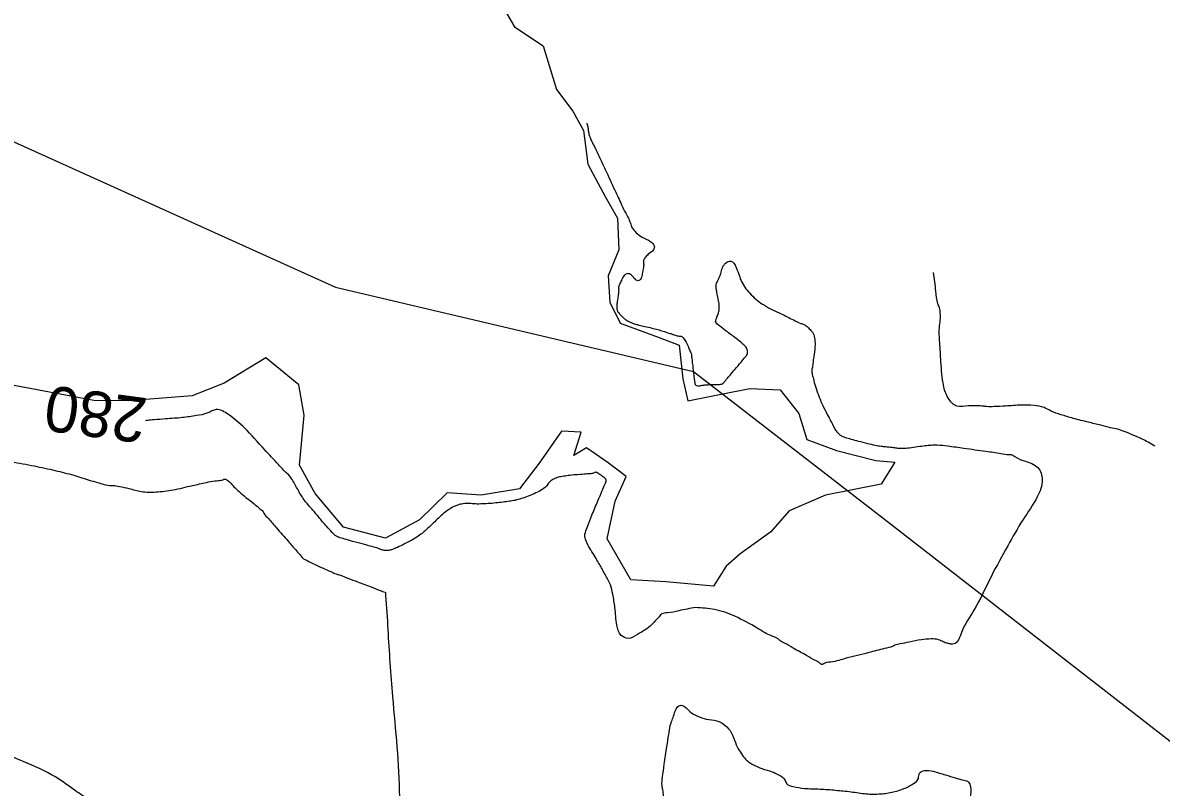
# Model space of a CAD drawing. Extents: x -478464 to -472469, y -1118040 to -1113785.
# Drawn here: x -474559.7 to -474459.6, y -1114309.4 to -1114242.1 of the extents above; entities that cross this region are included whole.
import ezdxf

# ---------------------------------------------------------------- set-up
doc = ezdxf.new("R2010")
doc.units = 0
for name, color, linetype in [('ObPÚ', 7, 'Continuous'), ('vodní plochy', 7, 'Continuous'), ('Vrstevnice_hlavni', 7, 'Continuous'), ('Vrstevnice_popis', 7, 'Continuous'), ('Vrstevnice_vedlejsi', 7, 'Continuous')]:
    doc.layers.add(name, color=color, linetype=linetype)

msp = doc.modelspace()

# ---------------------------------------------------------------- linework, layer by layer
at = {"layer": 'ObPÚ'}
msp.add_lwpolyline([(-474772.3, -1114123.51), (-474725.78, -1114135.53), (-474718.42, -1114145.53), (-474708.56, -1114152.16), (-474646.94, -1114193.59), (-474635.75, -1114203.01), (-474630.46, -1114207.45), (-474607.9, -1114226.4), (-474597.8, -1114234.88), (-474595.52, -1114236.79), (-474532.21, -1114265.39), (-474500.72, -1114272.81), (-474483.66, -1114286.03), (-474436.41, -1114322.73), (-474392.24, -1114354.32), (-474385.18, -1114363.49), (-474350.25, -1114409.55), (-474320.41, -1114444.98)], dxfattribs=at)
at = {"layer": 'vodní plochy'}
msp.add_lwpolyline([(-474517.381, -1114240.932), (-474516.46, -1114242.506), (-474513.936, -1114244.175), (-474512.76, -1114248.017), (-474511.348, -1114249.928), (-474510.41, -1114251.628), (-474510.002, -1114254.59), (-474508.503, -1114257.433), (-474507.396, -1114259.344), (-474507.298, -1114262.119), (-474508.215, -1114264.407), (-474508.087, -1114266.73), (-474507.171, -1114268.554), (-474503.731, -1114269.839), (-474501.992, -1114270.502), (-474501.655, -1114273.476), (-474501.211, -1114275.393), (-474498.281, -1114274.828), (-474495.76, -1114274.328), (-474493.088, -1114274.428), (-474491.467, -1114276.513), (-474490.761, -1114278.81), (-474488.132, -1114279.767), (-474484.696, -1114280.654), (-474483.01, -1114280.807), (-474484.205, -1114282.722), (-474489.099, -1114283.714), (-474492.302, -1114285.085), (-474493.914, -1114286.918), (-474496.657, -1114288.905), (-474497.848, -1114289.962), (-474498.971, -1114291.693), (-474503.166, -1114291.33), (-474506.247, -1114291.163), (-474508.316, -1114287.543), (-474507.623, -1114284.23), (-474506.65, -1114282.069), (-474508.229, -1114280.86), (-474510.129, -1114279.526), (-474511.24, -1114280.205), (-474510.616, -1114278.16), (-474512.335, -1114278.06), (-474514.308, -1114280.889), (-474516.042, -1114283.136), (-474519.386, -1114283.713), (-474522.388, -1114283.51), (-474524.836, -1114285.863), (-474527.818, -1114287.479), (-474531.516, -1114286.517), (-474534.015, -1114283.562), (-474535.382, -1114281.06), (-474534.978, -1114276.657), (-474535.44, -1114274.005), (-474538.342, -1114271.607), (-474542.018, -1114273.852), (-474544.819, -1114274.97), (-474550.403, -1114275.39), (-474553.469, -1114275.387), (-474569.725, -1114272.316)], dxfattribs=at)
at = {"layer": 'Vrstevnice_hlavni'}
for points in [[(-474510.104, -1114250.97), (-474510.091, -1114251.018), (-474510.014, -1114251.351), (-474509.96, -1114251.74), (-474509.859, -1114252.123), (-474509.71, -1114252.502), (-474509.513, -1114252.875), (-474509.103, -1114253.728), (-474508.479, -1114255.061), (-474507.64, -1114256.874), (-474507.041, -1114258.153), (-474506.68, -1114258.898), (-474506.557, -1114259.11), (-474506.422, -1114259.396), (-474506.273, -1114259.758)], [(-474506.273, -1114259.758), (-474506.111, -1114260.194), (-474505.763, -1114260.61), (-474505.229, -1114261.006), (-474504.508, -1114261.383), (-474504.179, -1114261.757), (-474504.243, -1114262.13), (-474504.7, -1114262.502), (-474504.996, -1114262.829), (-474505.131, -1114263.113), (-474505.106, -1114263.352), (-474505.131, -1114263.683), (-474505.208, -1114264.104), (-474505.337, -1114264.617), (-474505.543, -1114264.826), (-474505.826, -1114264.731), (-474506.188, -1114264.332), (-474506.515, -1114264.212), (-474506.807, -1114264.37), (-474507.065, -1114264.806), (-474507.234, -1114265.156), (-474507.313, -1114265.419), (-474507.303, -1114265.596), (-474507.322, -1114265.879), (-474507.37, -1114266.27), (-474507.447, -1114266.768), (-474507.472, -1114267.153), (-474507.445, -1114267.423), (-474507.367, -1114267.579), (-474507.232, -1114267.756), (-474507.04, -1114267.954), (-474506.791, -1114268.173), (-474506.538, -1114268.351), (-474506.281, -1114268.489), (-474506.019, -1114268.587), (-474505.642, -1114268.698), (-474505.148, -1114268.823), (-474504.538, -1114268.961), (-474503.987, -1114269.1), (-474503.496, -1114269.24), (-474503.063, -1114269.38), (-474502.726, -1114269.492), (-474502.482, -1114269.576), (-474502.333, -1114269.633), (-474502.17, -1114269.676), (-474501.991, -1114269.705), (-474501.797, -1114269.721), (-474501.592, -1114269.896), (-474501.375, -1114270.23), (-474501.147, -1114270.724), (-474500.992, -1114271.081), (-474500.91, -1114271.302), (-474500.9, -1114271.385), (-474500.867, -1114271.678), (-474500.811, -1114272.179), (-474500.732, -1114272.888), (-474500.665, -1114273.421), (-474500.611, -1114273.778), (-474500.569, -1114273.96), (-474500.449, -1114274.063), (-474500.25, -1114274.087), (-474499.973, -1114274.034), (-474499.649, -1114273.997), (-474499.277, -1114273.975), (-474498.859, -1114273.97), (-474498.548, -1114273.961), (-474498.344, -1114273.946), (-474498.248, -1114273.927), (-474498.127, -1114273.846), (-474497.98, -1114273.702), (-474497.808, -1114273.495), (-474497.51, -1114273.141), (-474497.084, -1114272.641), (-474496.532, -1114271.992), (-474496.161, -1114271.531), (-474495.97, -1114271.258), (-474495.959, -1114271.171), (-474495.97, -1114271.056), (-474496.002, -1114270.912), (-474496.054, -1114270.74), (-474496.379, -1114270.407), (-474496.976, -1114269.914), (-474497.844, -1114269.26), (-474498.433, -1114268.799), (-474498.743, -1114268.53), (-474498.773, -1114268.455), (-474498.745, -1114268.284), (-474498.658, -1114268.017), (-474498.512, -1114267.656), (-474498.456, -1114267.219), (-474498.49, -1114266.708), (-474498.615, -1114266.122), (-474498.698, -1114265.686), (-474498.74, -1114265.399), (-474498.741, -1114265.263), (-474498.601, -1114264.866), (-474498.32, -1114264.208)], [(-474498.32, -1114264.208), (-474497.898, -1114263.29), (-474497.45, -1114263.108), (-474496.974, -1114263.664), (-474496.471, -1114264.956), (-474495.643, -1114266.068), (-474494.49, -1114266.999), (-474493.012, -1114267.75), (-474491.938, -1114268.282), (-474491.268, -1114268.595), (-474491.003, -1114268.69), (-474490.736, -1114268.866), (-474490.468, -1114269.125), (-474490.199, -1114269.466), (-474490.054, -1114269.978), (-474490.035, -1114270.659), (-474490.141, -1114271.511), (-474490.224, -1114272.138), (-474490.283, -1114272.54), (-474490.318, -1114272.716), (-474490.272, -1114273.074), (-474490.145, -1114273.612), (-474489.937, -1114274.33), (-474489.669, -1114275.067), (-474489.341, -1114275.822), (-474488.953, -1114276.596), (-474488.629, -1114277.225), (-474488.369, -1114277.71), (-474488.171, -1114278.051), (-474487.936, -1114278.316), (-474487.664, -1114278.505), (-474487.355, -1114278.617), (-474486.879, -1114278.762), (-474486.236, -1114278.939), (-474485.427, -1114279.148), (-474484.756, -1114279.299), (-474484.222, -1114279.393), (-474483.825, -1114279.429), (-474483.433, -1114279.47), (-474483.048, -1114279.515), (-474482.668, -1114279.566), (-474482.171, -1114279.564), (-474481.556, -1114279.509), (-474480.824, -1114279.402), (-474480.202, -1114279.327), (-474479.69, -1114279.286), (-474479.289, -1114279.279), (-474478.373, -1114279.368), (-474476.943, -1114279.555), (-474474.999, -1114279.839), (-474473.676, -1114280.026), (-474472.974, -1114280.117), (-474472.894, -1114280.112), (-474472.442, -1114280.304), (-474471.618, -1114280.694), (-474470.422, -1114281.281), (-474470.043, -1114282.336), (-474470.481, -1114283.859), (-474471.737, -1114285.851), (-474473.084, -1114288.173), (-474474.521, -1114290.825), (-474476.049, -1114293.806), (-474477.152, -1114295.796), (-474477.829, -1114296.793), (-474478.08, -1114296.798), (-474478.387, -1114296.737), (-474478.749, -1114296.609), (-474479.166, -1114296.415), (-474479.808, -1114296.354), (-474480.673, -1114296.425), (-474481.762, -1114296.63), (-474482.541, -1114296.791), (-474483.009, -1114296.91), (-474483.167, -1114296.987), (-474483.934, -1114297.202), (-474485.309, -1114297.556), (-474487.293, -1114298.05), (-474488.628, -1114298.385), (-474489.313, -1114298.563), (-474489.347, -1114298.584), (-474489.387, -1114298.593), (-474489.431, -1114298.59), (-474489.479, -1114298.576), (-474489.521, -1114298.556), (-474489.556, -1114298.53), (-474489.585, -1114298.498), (-474489.993, -1114298.258), (-474490.78, -1114297.812), (-474491.946, -1114297.158), (-474492.73, -1114296.716), (-474493.13, -1114296.485), (-474493.147, -1114296.466), (-474493.81, -1114296.106), (-474495.121, -1114295.403), (-474497.078, -1114294.359), (-474498.879, -1114293.755), (-474500.524, -1114293.592)], [(-474536.346, -1114281.886), (-474536.522, -1114281.747), (-474537.225, -1114281.017), (-474538.455, -1114279.698), (-474540.213, -1114277.789), (-474541.632, -1114276.615), (-474542.713, -1114276.176), (-474543.454, -1114276.472), (-474544.442, -1114276.706), (-474545.676, -1114276.879), (-474547.155, -1114276.99), (-474548.174, -1114277.072), (-474548.732, -1114277.124), (-474548.929, -1114277.17)], [(-474500.524, -1114293.592), (-474502.013, -1114293.868), (-474503.01, -1114294.055), (-474503.516, -1114294.153), (-474503.529, -1114294.162), (-474503.682, -1114294.326), (-474503.975, -1114294.644), (-474504.406, -1114295.117), (-474504.967, -1114295.552), (-474505.657, -1114295.949), (-474506.475, -1114296.307), (-474507.077, -1114296.035), (-474507.463, -1114295.132), (-474507.633, -1114293.597), (-474507.823, -1114292.418), (-474508.034, -1114291.594), (-474508.265, -1114291.126), (-474508.493, -1114290.687), (-474508.716, -1114290.276), (-474508.935, -1114289.893), (-474509.213, -1114289.417), (-474509.551, -1114288.848), (-474509.949, -1114288.187), (-474510.196, -1114287.657), (-474510.291, -1114287.259), (-474510.235, -1114286.993), (-474510.024, -1114286.396), (-474509.656, -1114285.469), (-474509.133, -1114284.211), (-474508.753, -1114283.305), (-474508.518, -1114282.751), (-474508.427, -1114282.548), (-474508.415, -1114282.375), (-474508.484, -1114282.232), (-474508.632, -1114282.119), (-474508.79, -1114282.002), (-474508.958, -1114281.881), (-474509.136, -1114281.756), (-474509.289, -1114281.694), (-474509.418, -1114281.694), (-474509.522, -1114281.758), (-474509.837, -1114281.816), (-474510.362, -1114281.868), (-474511.097, -1114281.914), (-474511.734, -1114281.978), (-474512.273, -1114282.059), (-474512.714, -1114282.158), (-474513.091, -1114282.331), (-474513.404, -1114282.579), (-474513.653, -1114282.901), (-474514.044, -1114283.211), (-474514.577, -1114283.507), (-474515.252, -1114283.789), (-474515.867, -1114284.006), (-474516.421, -1114284.157), (-474516.915, -1114284.242), (-474517.475, -1114284.319), (-474518.102, -1114284.388), (-474518.795, -1114284.448), (-474519.441, -1114284.476), (-474520.041, -1114284.471), (-474520.593, -1114284.434), (-474521.106, -1114284.48), (-474521.579, -1114284.61), (-474522.013, -1114284.824), (-474522.458, -1114285.117), (-474522.914, -1114285.488), (-474523.382, -1114285.938), (-474523.8, -1114286.336), (-474524.169, -1114286.682), (-474524.487, -1114286.976), (-474524.931, -1114287.298), (-474525.498, -1114287.646), (-474526.191, -1114288.021), (-474526.758, -1114288.298), (-474527.199, -1114288.476), (-474527.514, -1114288.555), (-474527.829, -1114288.568), (-474528.142, -1114288.513), (-474528.455, -1114288.392), (-474528.987, -1114288.228), (-474529.739, -1114288.019), (-474530.711, -1114287.766), (-474531.433, -1114287.563), (-474531.907, -1114287.41), (-474532.131, -1114287.308), (-474532.501, -1114286.979), (-474533.016, -1114286.424), (-474533.677, -1114285.643), (-474534.2, -1114285.027), (-474534.587, -1114284.578), (-474534.837, -1114284.294), (-474535.124, -1114283.884), (-474535.448, -1114283.348), (-474535.809, -1114282.687), (-474536.109, -1114282.199), (-474536.346, -1114281.886)]]:
    msp.add_spline(points, degree=3, dxfattribs=at)
at = {"layer": 'Vrstevnice_vedlejsi'}
for points in [[(-474552.854, -1114311.249), (-474553.079, -1114311.087), (-474553.821, -1114310.574), (-474555.08, -1114309.711), (-474556.857, -1114308.497), (-474559.696, -1114307.123), (-474563.598, -1114305.587), (-474568.562, -1114303.891), (-474573.331, -1114301.997), (-474577.905, -1114299.906), (-474582.284, -1114297.617), (-474585.674, -1114295.919), (-474588.077, -1114294.812), (-474589.491, -1114294.296), (-474591.989, -1114293.662), (-474595.57, -1114292.908), (-474600.235, -1114292.036), (-474603.58, -1114291.444), (-474605.605, -1114291.133), (-474606.31, -1114291.102), (-474606.928, -1114291.027), (-474607.46, -1114290.909), (-474607.905, -1114290.747), (-474608.453, -1114290.591), (-474609.102, -1114290.44), (-474609.854, -1114290.294), (-474613.621, -1114289.328), (-474620.404, -1114287.542), (-474630.202, -1114284.937), (-474637.239, -1114282.941), (-474641.515, -1114281.554), (-474643.03, -1114280.777), (-474646.226, -1114278.86), (-474651.102, -1114275.804), (-474657.658, -1114271.609), (-474662.169, -1114268.281), (-474664.633, -1114265.821), (-474665.051, -1114264.228), (-474666.944, -1114260.949), (-474670.313, -1114255.984), (-474675.156, -1114249.332), (-474681.278, -1114245.965), (-474688.679, -1114245.885), (-474697.358, -1114249.09), (-474704.556, -1114251.174), (-474710.273, -1114252.136), (-474714.508, -1114251.976), (-474720.156, -1114252.317), (-474727.217, -1114253.156), (-474735.691, -1114254.496), (-474743.099, -1114255.448), (-474749.443, -1114256.012), (-474754.721, -1114256.188), (-474759.428, -1114257.754), (-474763.562, -1114260.711), (-474767.123, -1114265.059), (-474771.341, -1114269.134), (-474776.214, -1114272.938), (-474781.743, -1114276.469), (-474786.123, -1114279.544), (-474789.352, -1114282.163), (-474791.432, -1114284.326), (-474793.539, -1114286.068), (-474795.674, -1114287.39), (-474797.837, -1114288.291), (-474801.021, -1114290.603), (-474805.227, -1114294.326), (-474810.453, -1114299.461), (-474815.93, -1114304.595), (-474821.656, -1114309.73), (-474827.632, -1114314.865), (-474832.327, -1114319.021), (-474835.739, -1114322.197), (-474837.87, -1114324.394), (-474841.8, -1114328.201), (-474847.532, -1114333.618), (-474855.063, -1114340.645), (-474860.556, -1114345.784), (-474864.01, -1114349.037), (-474865.424, -1114350.402), (-474866.85, -1114351.834), (-474868.286, -1114353.332), (-474869.734, -1114354.897), (-474871.228, -1114357.206), (-474872.768, -1114360.258), (-474874.355, -1114364.053), (-474875.677, -1114367.182), (-474876.734, -1114369.645), (-474877.527, -1114371.441), (-474878.751, -1114373.179), (-474880.405, -1114374.858), (-474882.489, -1114376.478), (-474884.757, -1114377.858), (-474887.208, -1114379), (-474889.844, -1114379.903), (-474893.032, -1114381.02), (-474896.771, -1114382.352)], [(-474620.341, -1114261.799), (-474618.559, -1114262.645), (-474617.158, -1114263.319), (-474616.138, -1114263.821), (-474615.498, -1114264.15), (-474614.425, -1114264.619), (-474612.918, -1114265.229), (-474610.977, -1114265.98), (-474609.537, -1114266.741), (-474608.6, -1114267.514), (-474608.165, -1114268.297), (-474607.008, -1114269.493), (-474605.13, -1114271.101), (-474602.53, -1114273.123), (-474600.61, -1114274.596), (-474599.369, -1114275.522), (-474598.808, -1114275.899), (-474598.164, -1114276.165), (-474597.435, -1114276.321), (-474596.623, -1114276.365), (-474595.719, -1114276.405), (-474594.722, -1114276.441), (-474593.634, -1114276.474), (-474592.211, -1114276.487), (-474590.452, -1114276.482), (-474588.358, -1114276.458), (-474586.824, -1114276.467), (-474585.851, -1114276.509), (-474585.439, -1114276.584), (-474584.626, -1114276.512), (-474583.414, -1114276.294), (-474581.803, -1114275.929), (-474580.635, -1114275.65), (-474579.911, -1114275.458), (-474579.631, -1114275.351), (-474579.116, -1114275.345), (-474578.366, -1114275.438), (-474577.382, -1114275.631), (-474576.639, -1114275.783), (-474576.138, -1114275.892), (-474575.878, -1114275.958), (-474575.186, -1114276.211), (-474574.064, -1114276.649), (-474572.511, -1114277.273), (-474570.896, -1114277.903), (-474569.219, -1114278.538), (-474567.479, -1114279.179), (-474565.99, -1114279.669), (-474564.75, -1114280.007), (-474563.76, -1114280.194), (-474562.421, -1114280.444), (-474560.735, -1114280.756), (-474558.7, -1114281.13), (-474556.865, -1114281.529), (-474555.23, -1114281.953), (-474553.795, -1114282.401), (-474552.741, -1114282.7), (-474552.068, -1114282.85), (-474551.775, -1114282.85), (-474551.216, -1114282.937), (-474550.39, -1114283.112), (-474549.296, -1114283.374), (-474548, -1114283.417), (-474546.501, -1114283.243), (-474544.799, -1114282.851), (-474543.57, -1114282.583), (-474542.814, -1114282.438), (-474542.531, -1114282.416), (-474542.295, -1114282.383), (-474542.106, -1114282.339), (-474541.964, -1114282.282), (-474541.757, -1114282.366), (-474541.486, -1114282.59), (-474541.15, -1114282.956), (-474540.684, -1114283.391), (-474540.089, -1114283.896), (-474539.364, -1114284.471), (-474538.858, -1114284.895), (-474538.572, -1114285.168), (-474538.506, -1114285.289), (-474538.118, -1114285.761), (-474537.408, -1114286.583), (-474536.377, -1114287.756), (-474535.649, -1114288.586), (-474535.225, -1114289.072), (-474535.103, -1114289.216), (-474534.714, -1114289.453), (-474534.056, -1114289.783), (-474533.129, -1114290.207), (-474532.46, -1114290.503), (-474532.048, -1114290.671), (-474531.893, -1114290.711), (-474531.359, -1114290.905), (-474530.447, -1114291.251), (-474529.157, -1114291.751), (-474528.294, -1114292.084), (-474527.857, -1114292.249)], [(-474460.148, -1114279.397), (-474460.742, -1114279.036), (-474461.76, -1114278.543), (-474462.649, -1114278.167), (-474463.41, -1114277.908), (-474464.042, -1114277.764), (-474464.903, -1114277.556), (-474465.993, -1114277.284), (-474467.312, -1114276.947), (-474468.401, -1114276.62), (-474469.26, -1114276.301), (-474469.89, -1114275.993), (-474470.768, -1114275.817), (-474471.894, -1114275.774), (-474473.268, -1114275.865), (-474474.282, -1114275.911), (-474474.936, -1114275.913), (-474475.23, -1114275.87), (-474475.765, -1114275.848), (-474476.541, -1114275.847), (-474477.559, -1114275.866), (-474478.303, -1114275.185), (-474478.774, -1114273.804), (-474478.97, -1114271.723), (-474479.077, -1114270.108), (-474479.092, -1114268.962), (-474479.017, -1114268.283), (-474479.014, -1114267.705), (-474479.083, -1114267.23), (-474479.224, -1114266.856), (-474479.406, -1114265.75), (-474479.607, -1114264.11)], [(-474553.927, -1114400.416), (-474553.474, -1114399.617), (-474552.966, -1114398.863), (-474552.405, -1114398.155), (-474551.791, -1114397.492), (-474551.19, -1114396.826), (-474550.604, -1114396.156), (-474550.032, -1114395.484), (-474549.553, -1114394.754), (-474549.166, -1114393.968), (-474548.873, -1114393.124), (-474548.652, -1114392.233), (-474548.504, -1114391.292), (-474548.43, -1114390.304), (-474548.405, -1114389.279), (-474548.431, -1114388.218), (-474548.507, -1114387.121), (-474548.593, -1114386.176), (-474548.689, -1114385.383), (-474548.794, -1114384.743), (-474548.782, -1114383.719), (-474548.652, -1114382.312), (-474548.405, -1114380.522), (-474548.2, -1114379.213), (-474548.037, -1114378.385), (-474547.916, -1114378.037), (-474547.76, -1114377.133), (-474547.57, -1114375.673), (-474547.346, -1114373.655), (-474547.183, -1114372.254), (-474547.08, -1114371.47), (-474547.037, -1114371.302), (-474546.918, -1114370.892), (-474546.722, -1114370.241), (-474546.45, -1114369.347), (-474546.291, -1114368.58), (-474546.246, -1114367.94), (-474546.315, -1114367.427), (-474546.69, -1114366.615), (-474547.372, -1114365.504), (-474548.361, -1114364.094), (-474549.165, -1114362.891), (-474549.784, -1114361.892), (-474550.219, -1114361.1), (-474550.631, -1114360.14), (-474551.023, -1114359.011), (-474551.392, -1114357.714), (-474551.776, -1114356.302), (-474552.174, -1114354.773), (-474552.587, -1114353.128), (-474553.135, -1114351.671), (-474553.82, -1114350.403), (-474554.641, -1114349.324), (-474555.693, -1114348.305), (-474556.975, -1114347.347), (-474558.487, -1114346.449), (-474561.199, -1114344.714), (-474565.11, -1114342.144), (-474570.22, -1114338.737), (-474576.368, -1114334.802), (-474583.554, -1114330.338), (-474591.777, -1114325.345), (-474597.359, -1114321.978), (-474600.299, -1114320.235), (-474600.598, -1114320.118), (-474604.058, -1114319.093), (-474610.677, -1114317.161), (-474620.458, -1114314.323), (-474627.106, -1114312.405), (-474630.623, -1114311.409), (-474631.008, -1114311.334), (-474632.222, -1114311.03), (-474634.263, -1114310.497), (-474637.131, -1114309.734), (-474641.559, -1114307.935), (-474647.546, -1114305.101), (-474655.092, -1114301.231), (-474662.055, -1114298.079), (-474668.436, -1114295.643), (-474674.233, -1114293.924), (-474681.303, -1114292.66), (-474689.646, -1114291.85), (-474699.263, -1114291.494), (-474706.909, -1114291.13), (-474712.586, -1114290.757), (-474716.293, -1114290.376), (-474720.106, -1114290.354), (-474724.026, -1114290.69), (-474728.052, -1114291.384), (-474733.838, -1114291.971), (-474741.385, -1114292.45), (-474750.693, -1114292.823), (-474758.358, -1114294.589), (-474764.38, -1114297.75), (-474768.76, -1114302.305), (-474774.664, -1114306.585), (-474782.093, -1114310.591)], [(-474527.857, -1114292.249), (-474527.848, -1114292.246), (-474527.838, -1114292.25), (-474527.829, -1114292.26), (-474527.82, -1114292.276), (-474527.816, -1114292.295), (-474527.817, -1114292.316), (-474527.823, -1114292.341), (-474527.825, -1114292.385), (-474527.822, -1114292.451), (-474527.814, -1114292.537), (-474527.607, -1114295.525), (-474527.2, -1114301.416), (-474526.594, -1114310.208), (-474526.296, -1114316.187), (-474526.307, -1114319.353), (-474526.626, -1114319.706), (-474527.024, -1114320.209), (-474527.499, -1114320.863), (-474528.052, -1114321.666), (-474528.67, -1114322.429), (-474529.352, -1114323.149), (-474530.099, -1114323.829), (-474530.787, -1114324.494), (-474531.415, -1114325.147), (-474531.984, -1114325.786), (-474532.506, -1114326.547), (-474532.982, -1114327.429), (-474533.413, -1114328.433), (-474533.774, -1114329.243), (-474534.068, -1114329.859), (-474534.292, -1114330.28), (-474534.413, -1114330.645), (-474534.429, -1114330.954), (-474534.341, -1114331.206), (-474534.298, -1114331.524), (-474534.302, -1114331.909), (-474534.351, -1114332.36), (-474534.247, -1114333.15), (-474533.988, -1114334.277), (-474533.576, -1114335.742), (-474533.274, -1114336.852), (-474533.082, -1114337.608), (-474533.001, -1114338.009), (-474532.866, -1114338.393), (-474532.677, -1114338.762), (-474532.433, -1114339.115), (-474532.199, -1114339.736), (-474531.972, -1114340.626), (-474531.755, -1114341.785), (-474531.476, -1114343.1), (-474531.137, -1114344.571), (-474530.738, -1114346.198), (-474530.478, -1114347.34), (-474530.36, -1114347.996), (-474530.381, -1114348.167), (-474530.531, -1114348.934), (-474530.808, -1114350.296), (-474531.213, -1114352.254), (-474531.49, -1114353.58), (-474531.639, -1114354.273), (-474531.661, -1114354.334), (-474531.745, -1114354.654), (-474531.893, -1114355.233), (-474532.105, -1114356.07), (-474531.899, -1114356.479), (-474531.276, -1114356.46), (-474530.235, -1114356.014), (-474529.391, -1114355.438), (-474528.744, -1114354.734), (-474528.293, -1114353.901), (-474527.742, -1114353.153), (-474527.091, -1114352.49), (-474526.34, -1114351.913), (-474525.809, -1114351.284), (-474525.496, -1114350.604), (-474525.402, -1114349.871), (-474525.301, -1114348.594), (-474525.194, -1114346.772), (-474525.079, -1114344.407), (-474525.015, -1114342.777), (-474525.003, -1114341.884), (-474525.043, -1114341.728), (-474524.774, -1114341.021), (-474524.197, -1114339.765), (-474523.31, -1114337.959), (-474522.587, -1114336.38), (-474522.026, -1114335.028), (-474521.627, -1114333.903), (-474521.338, -1114332.941), (-474521.158, -1114332.141), (-474521.088, -1114331.503), (-474520.723, -1114330.765), (-474520.065, -1114329.927), (-474519.113, -1114328.99), (-474518.334, -1114328.213), (-474517.728, -1114327.597)], [(-474517.728, -1114327.597), (-474517.296, -1114327.142), (-474516.689, -1114326.587), (-474515.906, -1114325.931), (-474514.948, -1114325.176), (-474514.058, -1114324.619), (-474513.238, -1114324.261), (-474512.487, -1114324.102), (-474511.638, -1114323.813), (-474510.691, -1114323.392), (-474509.646, -1114322.841), (-474508.636, -1114322.314), (-474507.658, -1114321.81), (-474506.715, -1114321.331), (-474505.919, -1114320.851), (-474505.272, -1114320.371), (-474504.774, -1114319.89), (-474504.312, -1114319.361), (-474503.886, -1114318.785), (-474503.496, -1114318.162), (-474503.222, -1114317.469), (-474503.064, -1114316.707), (-474503.021, -1114315.876), (-474503.007, -1114315.07), (-474503.022, -1114314.291), (-474503.066, -1114313.537), (-474503.123, -1114312.722), (-474503.195, -1114311.846), (-474503.28, -1114310.909), (-474503.357, -1114310.167), (-474503.425, -1114309.621), (-474503.485, -1114309.269), (-474503.444, -1114308.519), (-474503.302, -1114307.371), (-474503.061, -1114305.825), (-474502.897, -1114304.768), (-474502.812, -1114304.202), (-474502.805, -1114304.125), (-474502.792, -1114304.05), (-474502.773, -1114303.974), (-474502.748, -1114303.9), (-474502.649, -1114303.627), (-474502.479, -1114303.156), (-474502.235, -1114302.486), (-474501.909, -1114302.198), (-474501.502, -1114302.292), (-474501.012, -1114302.768), (-474500.378, -1114303.137), (-474499.599, -1114303.399), (-474498.675, -1114303.555), (-474497.941, -1114303.953), (-474497.395, -1114304.592), (-474497.038, -1114305.473), (-474496.682, -1114306.182), (-474496.326, -1114306.721), (-474495.972, -1114307.088), (-474495.433, -1114307.431), (-474494.709, -1114307.75), (-474493.801, -1114308.046), (-474493.135, -1114308.365), (-474492.712, -1114308.706), (-474492.531, -1114309.071), (-474491.95, -1114309.334), (-474490.97, -1114309.495), (-474489.59, -1114309.556), (-474488.221, -1114309.656), (-474486.865, -1114309.797), (-474485.52, -1114309.978), (-474484.276, -1114309.983), (-474483.133, -1114309.813), (-474482.092, -1114309.467), (-474481.362, -1114309.075), (-474480.944, -1114308.638), (-474480.838, -1114308.155), (-474480.405, -1114307.94), (-474479.646, -1114307.994), (-474478.559, -1114308.316), (-474477.693, -1114308.569), (-474477.049, -1114308.755), (-474476.625, -1114308.872), (-474476.385, -1114309.232), (-474476.328, -1114309.834), (-474476.454, -1114310.68), (-474476.578, -1114311.751), (-474476.698, -1114313.048), (-474476.815, -1114314.57), (-474476.933, -1114315.804), (-474477.051, -1114316.749), (-474477.169, -1114317.406), (-474477.222, -1114318.147), (-474477.211, -1114318.972), (-474477.136, -1114319.882), (-474476.967, -1114320.745), (-474476.702, -1114321.563), (-474476.344, -1114322.334), (-474475.923, -1114323.062), (-474475.442, -1114323.748)]]:
    msp.add_spline(points, degree=3, dxfattribs=at)

# ---------------------------------------------------------------- texts
at = {"layer": 'Vrstevnice_popis'}
msp.add_text(' 280 ', height=4, rotation=172.37167, dxfattribs=at).set_placement((-474547.156, -1114275.394))

doc.saveas('drawing.dxf')
